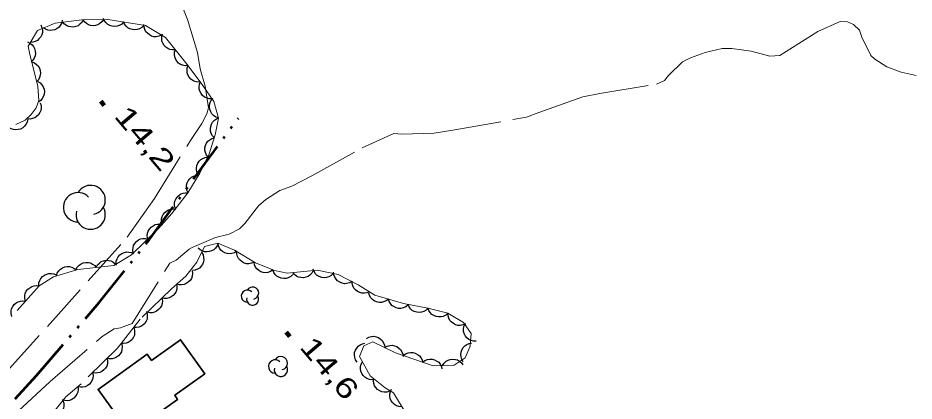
# Model space of a CAD drawing. Extents: x 386081 to 389416, y 5130568 to 5134082.
# Drawn here: x 387284.3 to 387416.1, y 5131680.4 to 5131736.8 of the extents above; entities that cross this region are included whole.
import ezdxf

# ---------------------------------------------------------------- set-up
doc = ezdxf.new("R2010")
doc.units = 0
doc.header["$LTSCALE"] = 1.2
for name, pattern in [('DASH_DOUBLE_DOT', [9.2, 5, -1.2, 0.3, -1.2, 0.3, -1.2]), ('DOT_DASHED', [7.7, 5, -1.2, 0.3, -1.2]), ('LONG_DASHED', [7.5, 6, -1.5])]:
    doc.linetypes.add(name, pattern=pattern)
for name, color, linetype, lineweight in [('2', 7, 'Continuous', 13), ('3', 7, 'Continuous', 140), ('31', 7, 'Continuous', 70), ('4', 7, 'DASH_DOUBLE_DOT', 53), ('44', 7, 'Continuous', 25)]:
    doc.layers.add(name, color=color, linetype=linetype, lineweight=lineweight)

msp = doc.modelspace()

# ---------------------------------------------------------------- linework, layer by layer
at = {"layer": '2', "linetype": 'LONG_DASHED'}
for points in [[(387269.77, 5131676.12), (387269.63, 5131676.91), (387269.63, 5131677.41), (387269.82, 5131677.96), (387270.19, 5131678.2), (387270.93, 5131678.19), (387271.42, 5131678.06), (387272.59, 5131677.37), (387273.45, 5131677.12), (387274, 5131677.05), (387274.68, 5131677.11), (387276.6, 5131678.01), (387300.37, 5131704.51), (387304.36, 5131710.23), (387309.65, 5131718.74), (387311.34, 5131721.25), (387312.06, 5131722.66), (387312.29, 5131723.53), (387311.84, 5131726.73), (387311.06, 5131729.3), (387310.67, 5131731.67), (387309.2, 5131736.53), (387308.44, 5131738.48)], [(387283.71, 5131678.38), (387289.04, 5131683.3), (387296.68, 5131689.94), (387298.44, 5131691.05), (387299.35, 5131691.22), (387301.07, 5131691.83), (387306.61, 5131700.7), (387307.56, 5131701.16), (387309.46, 5131702.78), (387309.9, 5131703.03), (387313.36, 5131704.5), (387315.34, 5131704.96), (387316.89, 5131705.73), (387317.66, 5131706.55), (387319.66, 5131709.16), (387320.74, 5131710.08), (387322.78, 5131711.38), (387324.56, 5131712.03), (387327.51, 5131713.53), (387334.89, 5131717.66), (387339.54, 5131719.75), (387340.74, 5131719.7), (387345.47, 5131719.84), (387348.22, 5131720.24), (387359.09, 5131722.17), (387360.86, 5131722.88), (387367.37, 5131725.16), (387369.85, 5131725.67), (387378.18, 5131727.01), (387379.38, 5131727.55), (387379.94, 5131728.29), (387382, 5131730.29), (387383.2, 5131730.92), (387385.35, 5131731.69), (387387.86, 5131732.26), (387389.27, 5131732.26), (387392.1, 5131731.87), (387394.86, 5131731.15), (387396.32, 5131731.26), (387401.89, 5131734.76), (387405.2, 5131736.26), (387406.25, 5131736.2), (387407.15, 5131735.82), (387408.03, 5131734.96), (387408.38, 5131733.94), (387409.69, 5131731.22), (387410.28, 5131730.69), (387412.04, 5131729.59), (387414.14, 5131728.8), (387416.39, 5131728.32)]]:
    msp.add_lwpolyline(points, dxfattribs=at)
at = {"layer": '3'}
for p, q in [((387296.46, 5131724.51), (387296.97, 5131723.9)), ((387323.74, 5131690.55), (387324.25, 5131689.94))]:
    msp.add_line(p, q, dxfattribs=at)
at = {"layer": '31', "lineweight": 35}
msp.add_lwpolyline([(387300.72, 5131675.65), (387307.76, 5131680.68), (387307.34, 5131681.27), (387311.78, 5131684.44), (387308.2, 5131689.45), (387303.94, 5131686.41), (387303.3, 5131687.31), (387296.07, 5131682.15)], close=True, dxfattribs=at)
at = {"layer": '4'}
msp.add_lwpolyline([(387250.15, 5131700.34), (387260.67, 5131688.59), (387266.34, 5131682.12), (387271.85, 5131676.5), (387273.58, 5131674.9), (387275.06, 5131674.07), (387276.49, 5131672.55), (387287.04, 5131684.2), (387296.23, 5131694.91), (387303.59, 5131704.13), (387316.71, 5131722.05)], dxfattribs=at)
at = {"layer": '44', "linetype": 'DOT_DASHED', "lineweight": 13}
for points in [[(387284.17, 5131693.75), (387287.4, 5131697.39), (387289.5, 5131698.72), (387293.08, 5131699.79), (387298.38, 5131700.35), (387300.97, 5131701.92), (387304.94, 5131705.8), (387306.93, 5131707.99), (387309.29, 5131711.03), (387311.03, 5131713.96), (387312.41, 5131716.77), (387313.29, 5131719.58), (387313.8, 5131722.03), (387313.08, 5131724.5), (387311.49, 5131726.84), (387309.17, 5131729.93), (387306, 5131733.89), (387303.05, 5131735.64), (387297.52, 5131736.56), (387293.7, 5131736.47), (387289.76, 5131736.02), (387287.16, 5131734.94), (387285.79, 5131732.62), (387286.03, 5131731.39), (387287.23, 5131726.72), (387287.34, 5131724.63), (387286.96, 5131723.53), (387286.22, 5131722.56), (387285.35, 5131721.71), (387283.99, 5131721.11)], [(387341.35, 5131678.54), (387339.52, 5131681.63), (387338.29, 5131682.38), (387336.09, 5131684.12), (387334.5, 5131686.96), (387335.13, 5131688.55), (387336.49, 5131689.15), (387339.81, 5131687.52), (387345.34, 5131685.62), (387348.42, 5131685.71), (387350.03, 5131686.8), (387350.78, 5131688.51), (387350.92, 5131690.35), (387349.82, 5131691.96), (387347.49, 5131693.33), (387344.54, 5131694.1), (387340.97, 5131694.75), (387336.78, 5131696.02), (387334.33, 5131697.52), (387331.38, 5131699.02), (387328.31, 5131699.67), (387323.87, 5131699.22), (387322.02, 5131699.61), (387319.2, 5131700.75), (387316.13, 5131702.62), (387313.67, 5131703.63), (387311.7, 5131703.15), (387310.57, 5131700.83), (387308.96, 5131698.77), (387306.85, 5131696.95)], [(387306.85, 5131696.95), (387302.26, 5131692.45), (387298.91, 5131688.19), (387293.58, 5131682.97), (387291.35, 5131681.04), (387289.36, 5131678.6), (387288.24, 5131676.28), (387287.49, 5131674.33), (387285.74, 5131670.42), (387284.86, 5131668.84), (387283.62, 5131667.62)]]:
    msp.add_lwpolyline(points, dxfattribs=at)
at = {"layer": '44'}
for points in [[(387290.8, 5131736.45), (387290.72, 5131736.04), (387290.52, 5131735.68), (387290.33, 5131735.42), (387290.05, 5131735.2), (387289.72, 5131735.03), (387289.35, 5131734.95), (387289.02, 5131734.91), (387288.68, 5131734.97), (387288.33, 5131735.1), (387288.03, 5131735.3)], [(387293.86, 5131736.49), (387293.67, 5131736.12), (387293.38, 5131735.83), (387293.12, 5131735.62), (387292.79, 5131735.5), (387292.43, 5131735.42), (387292.05, 5131735.44), (387291.73, 5131735.5), (387291.41, 5131735.66), (387291.11, 5131735.87), (387290.88, 5131736.15)], [(387296.86, 5131736.54), (387296.63, 5131736.19), (387296.32, 5131735.93), (387296.05, 5131735.75), (387295.71, 5131735.65), (387295.34, 5131735.61), (387294.96, 5131735.67), (387294.65, 5131735.75), (387294.35, 5131735.94), (387294.07, 5131736.18), (387293.86, 5131736.47)], [(387299.83, 5131736.18), (387299.54, 5131735.87), (387299.19, 5131735.67), (387298.88, 5131735.55), (387298.53, 5131735.52), (387298.16, 5131735.55), (387297.8, 5131735.67), (387297.5, 5131735.81), (387297.25, 5131736.05), (387297.02, 5131736.34), (387296.87, 5131736.67)], [(387287.64, 5131735.75), (387287.82, 5131735.37), (387287.88, 5131734.97), (387287.88, 5131734.64), (387287.79, 5131734.3), (387287.63, 5131733.97), (387287.38, 5131733.68), (387287.14, 5131733.45), (387286.83, 5131733.3), (387286.47, 5131733.19), (387286.11, 5131733.17)], [(387302.79, 5131735.68), (387302.5, 5131735.38), (387302.15, 5131735.18), (387301.84, 5131735.06), (387301.49, 5131735.02), (387301.12, 5131735.05), (387300.76, 5131735.18), (387300.46, 5131735.32), (387300.2, 5131735.56), (387299.98, 5131735.85), (387299.83, 5131736.18)], [(387305.4, 5131734.25), (387305.02, 5131734.07), (387304.62, 5131734.01), (387304.29, 5131734), (387303.95, 5131734.1), (387303.62, 5131734.26), (387303.33, 5131734.51), (387303.1, 5131734.74), (387302.95, 5131735.06), (387302.84, 5131735.42), (387302.82, 5131735.78)], [(387307.44, 5131732.09), (387307.02, 5131732.06), (387306.63, 5131732.15), (387306.32, 5131732.26), (387306.03, 5131732.47), (387305.78, 5131732.73), (387305.59, 5131733.07), (387305.46, 5131733.37), (387305.43, 5131733.72), (387305.46, 5131734.09), (387305.56, 5131734.43)], [(387285.67, 5131733.24), (387286.05, 5131733.08), (387286.36, 5131732.82), (387286.59, 5131732.58), (387286.74, 5131732.26), (387286.84, 5131731.9), (387286.85, 5131731.52), (387286.83, 5131731.2), (387286.69, 5131730.87), (387286.5, 5131730.55), (387286.24, 5131730.3)], [(387309.31, 5131729.75), (387308.9, 5131729.72), (387308.5, 5131729.8), (387308.19, 5131729.92), (387307.91, 5131730.13), (387307.65, 5131730.39), (387307.47, 5131730.73), (387307.34, 5131731.03), (387307.31, 5131731.38), (387307.33, 5131731.75), (387307.44, 5131732.09)], [(387286.31, 5131730.31), (387286.7, 5131730.17), (387287.03, 5131729.93), (387287.26, 5131729.7), (387287.44, 5131729.39), (387287.56, 5131729.04), (387287.59, 5131728.66), (387287.58, 5131728.34), (387287.47, 5131728), (387287.29, 5131727.68), (387287.05, 5131727.41)], [(387311.11, 5131727.35), (387310.69, 5131727.33), (387310.3, 5131727.43), (387309.99, 5131727.55), (387309.71, 5131727.77), (387309.47, 5131728.04), (387309.29, 5131728.38), (387309.17, 5131728.68), (387309.15, 5131729.04), (387309.19, 5131729.41), (387309.31, 5131729.75)], [(387287.19, 5131727.43), (387287.55, 5131727.21), (387287.82, 5131726.91), (387288.01, 5131726.64), (387288.12, 5131726.3), (387288.17, 5131725.94), (387288.12, 5131725.56), (387288.05, 5131725.24), (387287.87, 5131724.94), (387287.64, 5131724.65), (387287.35, 5131724.43)], [(387312.82, 5131724.88), (387312.4, 5131724.88), (387312.01, 5131725), (387311.71, 5131725.14), (387311.45, 5131725.37), (387311.21, 5131725.65), (387311.05, 5131726), (387310.95, 5131726.31), (387310.95, 5131726.66), (387311, 5131727.03), (387311.13, 5131727.36)], [(387313.79, 5131722.06), (387313.39, 5131722.19), (387313.06, 5131722.42), (387312.81, 5131722.65), (387312.63, 5131722.95), (387312.5, 5131723.29), (387312.45, 5131723.67), (387312.45, 5131724), (387312.56, 5131724.34), (387312.72, 5131724.67), (387312.95, 5131724.94)], [(387287.55, 5131724.3), (387287.68, 5131723.9), (387287.69, 5131723.5), (387287.66, 5131723.17), (387287.52, 5131722.84), (387287.32, 5131722.53), (387287.04, 5131722.27), (387286.78, 5131722.07), (387286.45, 5131721.96), (387286.09, 5131721.89), (387285.73, 5131721.91)], [(387285.72, 5131721.87), (387285.64, 5131721.46), (387285.46, 5131721.1), (387285.27, 5131720.83), (387285, 5131720.61), (387284.67, 5131720.43), (387284.3, 5131720.34), (387283.98, 5131720.29), (387283.63, 5131720.35), (387283.28, 5131720.47), (387282.97, 5131720.66)], [(387313.2, 5131719.13), (387312.9, 5131719.43), (387312.72, 5131719.79), (387312.61, 5131720.1), (387312.59, 5131720.45), (387312.63, 5131720.82), (387312.77, 5131721.17), (387312.92, 5131721.46), (387313.17, 5131721.71), (387313.47, 5131721.93), (387313.81, 5131722.06)], [(387312.26, 5131716.28), (387312, 5131716.6), (387311.85, 5131716.98), (387311.77, 5131717.3), (387311.78, 5131717.65), (387311.86, 5131718.01), (387312.03, 5131718.36), (387312.21, 5131718.63), (387312.49, 5131718.85), (387312.81, 5131719.04), (387313.15, 5131719.14)], [(387310.86, 5131713.61), (387310.65, 5131713.98), (387310.56, 5131714.37), (387310.53, 5131714.7), (387310.6, 5131715.05), (387310.73, 5131715.39), (387310.96, 5131715.7), (387311.18, 5131715.94), (387311.48, 5131716.12), (387311.83, 5131716.26), (387312.18, 5131716.31)], [(387309.3, 5131711.05), (387309.12, 5131711.43), (387309.06, 5131711.83), (387309.06, 5131712.16), (387309.16, 5131712.5), (387309.32, 5131712.83), (387309.56, 5131713.12), (387309.8, 5131713.35), (387310.12, 5131713.5), (387310.47, 5131713.61), (387310.83, 5131713.63)], [(387307.46, 5131708.68), (387307.33, 5131709.07), (387307.32, 5131709.48), (387307.36, 5131709.81), (387307.5, 5131710.13), (387307.7, 5131710.44), (387307.98, 5131710.7), (387308.24, 5131710.9), (387308.58, 5131711.01), (387308.94, 5131711.07), (387309.3, 5131711.05)], [(387305.5, 5131706.41), (387305.4, 5131706.82), (387305.42, 5131707.23), (387305.48, 5131707.55), (387305.65, 5131707.86), (387305.87, 5131708.16), (387306.17, 5131708.39), (387306.45, 5131708.57), (387306.79, 5131708.65), (387307.16, 5131708.68), (387307.51, 5131708.63)], [(387303.39, 5131704.28), (387303.31, 5131704.69), (387303.36, 5131705.1), (387303.44, 5131705.42), (387303.62, 5131705.72), (387303.86, 5131706), (387304.18, 5131706.22), (387304.46, 5131706.37), (387304.81, 5131706.44), (387305.18, 5131706.45), (387305.53, 5131706.38)], [(387301.24, 5131702.19), (387301.17, 5131702.6), (387301.21, 5131703), (387301.3, 5131703.32), (387301.48, 5131703.62), (387301.72, 5131703.9), (387302.03, 5131704.12), (387302.32, 5131704.28), (387302.66, 5131704.34), (387303.03, 5131704.35), (387303.39, 5131704.28)], [(387313.71, 5131703.64), (387313.56, 5131703.25), (387313.32, 5131702.92), (387313.08, 5131702.69), (387312.77, 5131702.52), (387312.42, 5131702.4), (387312.04, 5131702.38), (387311.72, 5131702.39), (387311.38, 5131702.51), (387311.06, 5131702.69), (387310.79, 5131702.93)], [(387316.48, 5131702.48), (387316.13, 5131702.24), (387315.74, 5131702.13), (387315.42, 5131702.08), (387315.07, 5131702.12), (387314.72, 5131702.23), (387314.39, 5131702.43), (387314.13, 5131702.64), (387313.94, 5131702.93), (387313.78, 5131703.26), (387313.71, 5131703.62)], [(387298.73, 5131700.56), (387298.75, 5131700.98), (387298.89, 5131701.36), (387299.04, 5131701.65), (387299.28, 5131701.91), (387299.58, 5131702.13), (387299.94, 5131702.27), (387300.25, 5131702.35), (387300.6, 5131702.34), (387300.97, 5131702.27), (387301.29, 5131702.12)], [(387311.29, 5131702.31), (387311.5, 5131701.95), (387311.59, 5131701.55), (387311.62, 5131701.22), (387311.56, 5131700.88), (387311.42, 5131700.53), (387311.2, 5131700.22), (387310.98, 5131699.98), (387310.68, 5131699.8), (387310.33, 5131699.67), (387309.98, 5131699.61)], [(387319.02, 5131700.86), (387318.64, 5131700.69), (387318.23, 5131700.63), (387317.9, 5131700.63), (387317.57, 5131700.73), (387317.24, 5131700.9), (387316.95, 5131701.15), (387316.72, 5131701.39), (387316.57, 5131701.71), (387316.47, 5131702.06), (387316.45, 5131702.42)], [(387292.82, 5131699.76), (387293.02, 5131700.13), (387293.3, 5131700.42), (387293.57, 5131700.62), (387293.89, 5131700.74), (387294.26, 5131700.82), (387294.64, 5131700.79), (387294.96, 5131700.74), (387295.27, 5131700.57), (387295.57, 5131700.35), (387295.8, 5131700.08)], [(387295.8, 5131700.08), (387296, 5131700.45), (387296.29, 5131700.73), (387296.55, 5131700.93), (387296.88, 5131701.06), (387297.24, 5131701.13), (387297.62, 5131701.11), (387297.94, 5131701.05), (387298.26, 5131700.89), (387298.55, 5131700.67), (387298.79, 5131700.39)], [(387321.78, 5131699.71), (387321.44, 5131699.47), (387321.05, 5131699.35), (387320.72, 5131699.3), (387320.37, 5131699.34), (387320.02, 5131699.45), (387319.69, 5131699.65), (387319.43, 5131699.85), (387319.23, 5131700.14), (387319.08, 5131700.48), (387319, 5131700.83)], [(387289.95, 5131698.86), (387290.08, 5131699.25), (387290.31, 5131699.59), (387290.53, 5131699.84), (387290.83, 5131700.02), (387291.17, 5131700.16), (387291.55, 5131700.2), (387291.88, 5131700.21), (387292.22, 5131700.11), (387292.55, 5131699.94), (387292.83, 5131699.71)], [(387309.92, 5131699.59), (387309.96, 5131699.18), (387309.89, 5131698.78), (387309.79, 5131698.46), (387309.59, 5131698.17), (387309.33, 5131697.91), (387309.01, 5131697.71), (387308.71, 5131697.57), (387308.36, 5131697.53), (387307.99, 5131697.54), (387307.64, 5131697.63)], [(387324.7, 5131699.04), (387324.4, 5131698.75), (387324.04, 5131698.57), (387323.73, 5131698.46), (387323.38, 5131698.44), (387323.01, 5131698.48), (387322.66, 5131698.63), (387322.37, 5131698.78), (387322.12, 5131699.03), (387321.91, 5131699.33), (387321.77, 5131699.66)], [(387327.7, 5131699.61), (387327.51, 5131699.24), (387327.22, 5131698.95), (387326.95, 5131698.75), (387326.62, 5131698.63), (387326.26, 5131698.56), (387325.88, 5131698.59), (387325.56, 5131698.64), (387325.25, 5131698.81), (387324.95, 5131699.03), (387324.72, 5131699.31)], [(387330.65, 5131699.17), (387330.35, 5131698.88), (387329.99, 5131698.7), (387329.67, 5131698.59), (387329.32, 5131698.57), (387328.96, 5131698.62), (387328.6, 5131698.76), (387328.31, 5131698.91), (387328.06, 5131699.16), (387327.85, 5131699.46), (387327.71, 5131699.8)], [(387333.39, 5131698), (387333.02, 5131697.8), (387332.62, 5131697.71), (387332.3, 5131697.69), (387331.95, 5131697.76), (387331.61, 5131697.9), (387331.3, 5131698.13), (387331.06, 5131698.35), (387330.89, 5131698.65), (387330.76, 5131699), (387330.71, 5131699.36)], [(387287.37, 5131697.37), (387287.38, 5131697.79), (387287.51, 5131698.17), (387287.65, 5131698.47), (387287.89, 5131698.73), (387288.19, 5131698.95), (387288.54, 5131699.1), (387288.85, 5131699.19), (387289.21, 5131699.18), (387289.57, 5131699.12), (387289.9, 5131698.97)], [(387335.99, 5131696.51), (387335.61, 5131696.33), (387335.2, 5131696.28), (387334.87, 5131696.28), (387334.54, 5131696.38), (387334.21, 5131696.55), (387333.92, 5131696.8), (387333.69, 5131697.04), (387333.55, 5131697.36), (387333.45, 5131697.71), (387333.43, 5131698.07)], [(387285.38, 5131695.12), (387285.28, 5131695.52), (387285.3, 5131695.93), (387285.36, 5131696.25), (387285.51, 5131696.57), (387285.73, 5131696.86), (387286.03, 5131697.1), (387286.31, 5131697.28), (387286.65, 5131697.37), (387287.02, 5131697.41), (387287.37, 5131697.36)], [(387307.6, 5131697.68), (387307.67, 5131697.27), (387307.63, 5131696.87), (387307.55, 5131696.55), (387307.37, 5131696.25), (387307.13, 5131695.97), (387306.81, 5131695.75), (387306.53, 5131695.59), (387306.18, 5131695.52), (387305.81, 5131695.51), (387305.46, 5131695.58)], [(387305.46, 5131695.58), (387305.53, 5131695.17), (387305.49, 5131694.77), (387305.4, 5131694.45), (387305.22, 5131694.15), (387304.98, 5131693.87), (387304.67, 5131693.65), (387304.38, 5131693.49), (387304.04, 5131693.42), (387303.67, 5131693.41), (387303.31, 5131693.48)], [(387338.76, 5131695.42), (387338.44, 5131695.16), (387338.06, 5131695), (387337.74, 5131694.92), (387337.39, 5131694.93), (387337.03, 5131695.01), (387336.68, 5131695.18), (387336.41, 5131695.35), (387336.18, 5131695.63), (387336, 5131695.95), (387335.89, 5131696.29)], [(387341.63, 5131694.55), (387341.31, 5131694.29), (387340.93, 5131694.13), (387340.61, 5131694.05), (387340.26, 5131694.06), (387339.9, 5131694.14), (387339.56, 5131694.31), (387339.28, 5131694.48), (387339.06, 5131694.76), (387338.87, 5131695.08), (387338.76, 5131695.42)], [(387283.39, 5131692.87), (387283.29, 5131693.28), (387283.31, 5131693.68), (387283.36, 5131694.01), (387283.52, 5131694.32), (387283.74, 5131694.62), (387284.04, 5131694.86), (387284.32, 5131695.04), (387284.66, 5131695.13), (387285.03, 5131695.16), (387285.38, 5131695.12)], [(387344.6, 5131694.09), (387344.31, 5131693.79), (387343.95, 5131693.59), (387343.64, 5131693.48), (387343.29, 5131693.45), (387342.93, 5131693.48), (387342.57, 5131693.61), (387342.27, 5131693.76), (387342.02, 5131694), (387341.8, 5131694.3), (387341.65, 5131694.63)], [(387347.5, 5131693.33), (387347.19, 5131693.05), (387346.82, 5131692.88), (387346.5, 5131692.79), (387346.15, 5131692.79), (387345.79, 5131692.85), (387345.44, 5131693.01), (387345.16, 5131693.17), (387344.92, 5131693.43), (387344.72, 5131693.74), (387344.6, 5131694.08)], [(387303.17, 5131693.61), (387303.3, 5131693.21), (387303.31, 5131692.81), (387303.27, 5131692.48), (387303.13, 5131692.16), (387302.93, 5131691.85), (387302.64, 5131691.59), (387302.38, 5131691.4), (387302.04, 5131691.29), (387301.68, 5131691.23), (387301.32, 5131691.25)], [(387350.09, 5131691.8), (387349.71, 5131691.62), (387349.31, 5131691.56), (387348.98, 5131691.56), (387348.64, 5131691.65), (387348.31, 5131691.81), (387348.01, 5131692.06), (387347.79, 5131692.29), (387347.63, 5131692.61), (387347.53, 5131692.96), (387347.5, 5131693.32)], [(387351.69, 5131689.23), (387351.27, 5131689.22), (387350.88, 5131689.34), (387350.58, 5131689.48), (387350.31, 5131689.71), (387350.08, 5131689.99), (387349.92, 5131690.34), (387349.81, 5131690.65), (387349.81, 5131691), (387349.86, 5131691.37), (387350, 5131691.7)], [(387301.32, 5131691.25), (387301.45, 5131690.85), (387301.45, 5131690.45), (387301.41, 5131690.12), (387301.27, 5131689.8), (387301.07, 5131689.49), (387300.79, 5131689.23), (387300.52, 5131689.04), (387300.19, 5131688.93), (387299.82, 5131688.87), (387299.46, 5131688.89)], [(387299.55, 5131688.82), (387299.63, 5131688.41), (387299.58, 5131688), (387299.5, 5131687.68), (387299.32, 5131687.38), (387299.08, 5131687.1), (387298.76, 5131686.88), (387298.48, 5131686.72), (387298.13, 5131686.66), (387297.76, 5131686.65), (387297.41, 5131686.72)], [(387334.18, 5131686.14), (387333.94, 5131686.49), (387333.82, 5131686.87), (387333.76, 5131687.2), (387333.8, 5131687.55), (387333.91, 5131687.9), (387334.11, 5131688.23), (387334.31, 5131688.49), (387334.59, 5131688.69), (387334.93, 5131688.85), (387335.28, 5131688.93)], [(387335.52, 5131689.62), (387335.89, 5131689.83), (387336.28, 5131689.92), (387336.61, 5131689.95), (387336.96, 5131689.88), (387337.3, 5131689.75), (387337.61, 5131689.53), (387337.85, 5131689.31), (387338.03, 5131689.01), (387338.17, 5131688.66), (387338.22, 5131688.3)], [(387349.77, 5131686.21), (387349.55, 5131686.56), (387349.44, 5131686.95), (387349.39, 5131687.28), (387349.45, 5131687.63), (387349.57, 5131687.98), (387349.78, 5131688.3), (387349.98, 5131688.55), (387350.28, 5131688.74), (387350.62, 5131688.89), (387350.97, 5131688.95)], [(387338.22, 5131688.3), (387338.58, 5131688.51), (387338.97, 5131688.6), (387339.3, 5131688.63), (387339.65, 5131688.56), (387339.99, 5131688.43), (387340.3, 5131688.2), (387340.55, 5131687.99), (387340.73, 5131687.68), (387340.86, 5131687.34), (387340.91, 5131686.98)], [(387340.97, 5131687.12), (387341.3, 5131687.37), (387341.68, 5131687.51), (387342.01, 5131687.58), (387342.36, 5131687.56), (387342.72, 5131687.47), (387343.05, 5131687.29), (387343.32, 5131687.1), (387343.54, 5131686.82), (387343.71, 5131686.49), (387343.8, 5131686.15)], [(387297.41, 5131686.72), (387297.48, 5131686.31), (387297.44, 5131685.9), (387297.35, 5131685.58), (387297.17, 5131685.28), (387296.93, 5131685), (387296.62, 5131684.78), (387296.33, 5131684.62), (387295.99, 5131684.56), (387295.62, 5131684.55), (387295.26, 5131684.62)], [(387336.4, 5131683.57), (387335.98, 5131683.61), (387335.6, 5131683.76), (387335.31, 5131683.92), (387335.07, 5131684.17), (387334.86, 5131684.48), (387334.73, 5131684.84), (387334.66, 5131685.16), (387334.68, 5131685.51), (387334.77, 5131685.87), (387334.93, 5131686.19)], [(387343.8, 5131686.15), (387344.14, 5131686.4), (387344.52, 5131686.54), (387344.84, 5131686.61), (387345.19, 5131686.58), (387345.55, 5131686.49), (387345.89, 5131686.31), (387346.16, 5131686.13), (387346.37, 5131685.85), (387346.55, 5131685.52), (387346.64, 5131685.17)], [(387346.72, 5131685.66), (387346.94, 5131686.01), (387347.25, 5131686.28), (387347.53, 5131686.46), (387347.86, 5131686.56), (387348.23, 5131686.6), (387348.61, 5131686.55), (387348.93, 5131686.47), (387349.22, 5131686.28), (387349.5, 5131686.04), (387349.71, 5131685.75)], [(387295.26, 5131684.62), (387295.34, 5131684.21), (387295.29, 5131683.8), (387295.21, 5131683.48), (387295.03, 5131683.18), (387294.79, 5131682.9), (387294.48, 5131682.68), (387294.19, 5131682.53), (387293.84, 5131682.46), (387293.47, 5131682.45), (387293.12, 5131682.52)], [(387338.93, 5131681.87), (387338.54, 5131681.74), (387338.13, 5131681.74), (387337.8, 5131681.78), (387337.48, 5131681.92), (387337.17, 5131682.12), (387336.91, 5131682.41), (387336.72, 5131682.67), (387336.61, 5131683.01), (387336.55, 5131683.37), (387336.58, 5131683.73)], [(387293.09, 5131682.55), (387293.14, 5131682.13), (387293.07, 5131681.73), (387292.97, 5131681.42), (387292.77, 5131681.13), (387292.52, 5131680.86), (387292.19, 5131680.66), (387291.89, 5131680.53), (387291.54, 5131680.48), (387291.17, 5131680.49), (387290.82, 5131680.59)], [(387340.73, 5131679.58), (387340.32, 5131679.61), (387339.93, 5131679.75), (387339.64, 5131679.9), (387339.39, 5131680.15), (387339.18, 5131680.45), (387339.04, 5131680.81), (387338.96, 5131681.12), (387338.97, 5131681.47), (387339.05, 5131681.84), (387339.2, 5131682.16)], [(387290.91, 5131680.5), (387291.03, 5131680.1), (387291.03, 5131679.7), (387290.99, 5131679.37), (387290.84, 5131679.05), (387290.63, 5131678.74), (387290.34, 5131678.49), (387290.08, 5131678.3), (387289.74, 5131678.2), (387289.37, 5131678.15), (387289.02, 5131678.18)]]:
    msp.add_lwpolyline(points, dxfattribs=at)
for centre, radius, start, end in [((387294.981, 5131709.997), 2.157, 282.26917, 149.72626), ((387293.126, 5131708.919), 2.157, 44.11537, 269.80396), ((387294.981, 5131707.841), 2.157, 166.93686, 29.62122), ((387318.025, 5131695.86), 0.893, 44.11537, 269.80396), ((387318.793, 5131696.307), 0.893, 282.26917, 149.72626), ((387318.793, 5131695.414), 0.893, 166.93686, 29.62122), ((387322.106, 5131685.512), 0.981, 44.11537, 269.80396), ((387322.95, 5131686.003), 0.981, 282.26917, 149.72626), ((387322.95, 5131685.022), 0.981, 166.93686, 29.62122)]:
    msp.add_arc(centre, radius, start, end, dxfattribs=at)

# ---------------------------------------------------------------- texts
at = {"layer": '3'}
for s, width, p in [('14,2   ', 1.4, (387298.29, 5131722.29)), ('14,6   ', 1.35, (387325.57, 5131688.33))]:
    msp.add_text(s, height=3, rotation=310.294, dxfattribs=dict(at, width=width)).set_placement(p)

doc.saveas('drawing.dxf')
